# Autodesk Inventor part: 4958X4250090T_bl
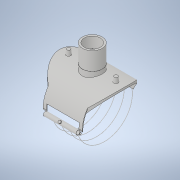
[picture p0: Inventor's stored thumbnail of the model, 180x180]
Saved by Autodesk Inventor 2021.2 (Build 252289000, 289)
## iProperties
Created: 2020-06
Part Number: 4958X4250090T_bl
Material: Generic
Description: Plasson Branch Saddle 250x90
Document SubType Name: Modeling
Designer: KIM
Density: 1 g/cm^3
Appearance: Default
Author: KIM
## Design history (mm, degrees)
derived "4958X4.ipt"
feature "Solid1::4958X4.ipt" dims "ScaleForDerivedMember" = 10
tag "TaggingFeature1"
body "Solid1"
other parameters: "d0" = 295 [user parameter], "d3" = 268 [user parameter], "d4" = 109 [user parameter], "d7" = 73 [user parameter], "d9" = 81 [user parameter], "d10" = 0.5 [user parameter], "d11" = 1 [user parameter], "d12" = 27.25 [user parameter], "d13" = 16 [user parameter], "d14" = 8 [user parameter], "d16" = 10 deg [user parameter], "d17" = 10 deg [user parameter], "d19" = 0 [user parameter], "d23" = 0 [user parameter], "d26" = 0 [user parameter], "d27" = 177 [user parameter], "d28" = 0 [user parameter], "d29" = 147.5 [user parameter], "d30" = 0 [user parameter], "d31" = 1 [user parameter], "d32" = 1 [user parameter], "d33" = 19.2 [user parameter], "d34" = 9.6 [user parameter], "d35" = 45 deg [user parameter], "d36" = 147.5 [user parameter], "d37" = 0 [user parameter], "d38" = 5 [user parameter], "d39" = 85 deg [user parameter], "d40" = 27.25 [user parameter], "d41" = 16 [user parameter], "d42" = 107.27273 [user parameter], "d49" = 3 [user parameter], "d50" = 6 [user parameter], "d51" = 5 [user parameter], "d54" = 0 [user parameter], "d57" = 35 deg [user parameter], "d60" = 18.4375 [user parameter], "d61" = 1 [user parameter], "d62" = 90 deg [user parameter], "d63" = 2 [user parameter], "d64" = 0 [user parameter], "d65" = 0 [user parameter], "d68" = 36.875 [user parameter], "d70" = 0.57711 [user parameter], "d71" = 10 deg [user parameter], "d73" = 3.15 [user parameter], "L" = 295 [user parameter], "LS" = 81 [user parameter], "H1" = 109 [user parameter], "Dt" = 16 [user parameter], "di" = 73 [user parameter], "d72" = 9 [user parameter]
